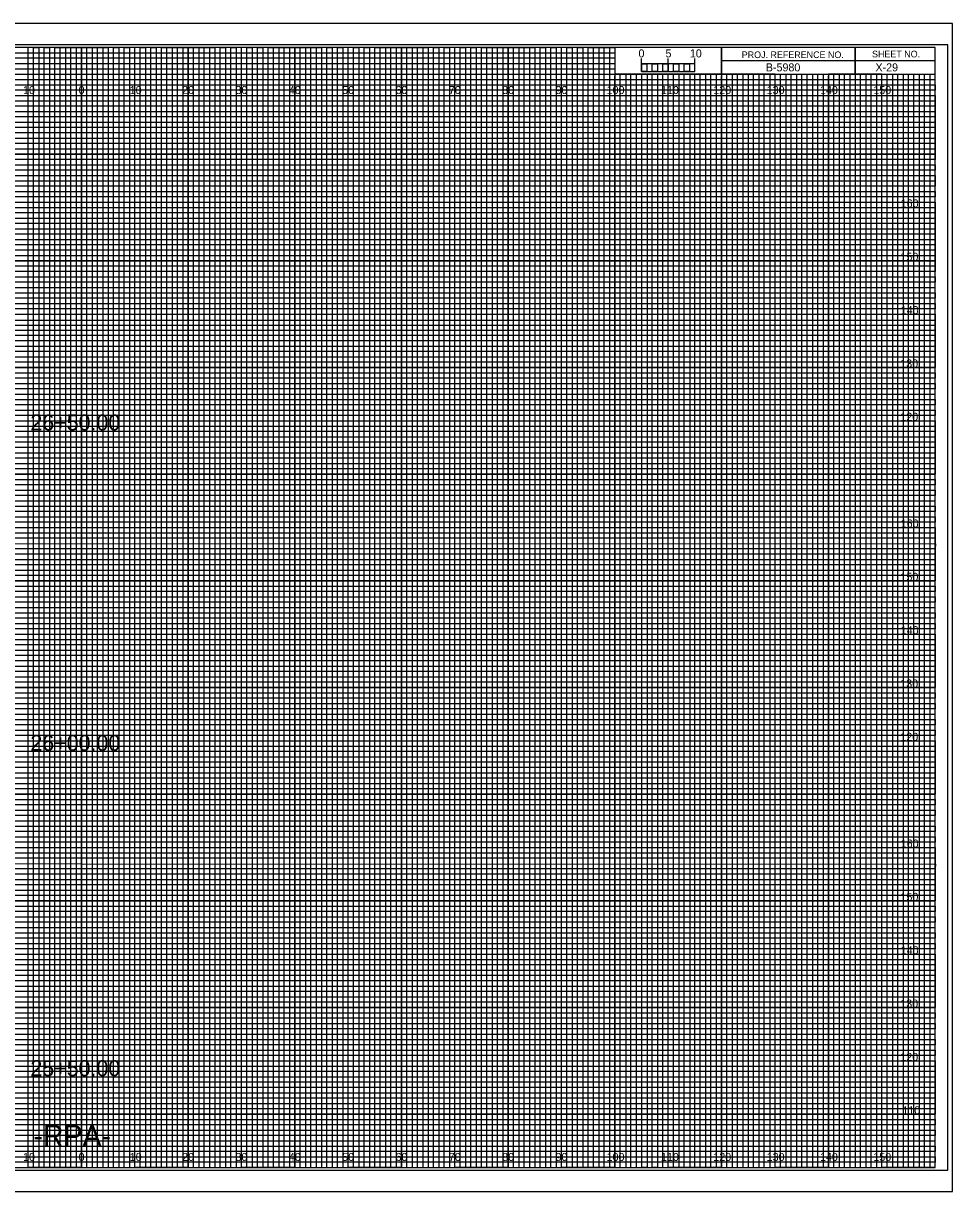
# Model space of a CAD drawing. Extents: x -13 to 323, y -5 to 1974.
# Drawn here: x 149.1 to 323.3, y 1095.5 to 1314.5 of the extents above; entities that cross this region are included whole.
import ezdxf

# ---------------------------------------------------------------- set-up
doc = ezdxf.new("R2010")
doc.units = 0
for name, color, linetype in [('Exist Cross Section Cell', 7, 'Continuous'), ('Exist XS Center Line Elevation Label', 7, 'Continuous'), ('Exist XS Ground Line', 7, 'Continuous'), ('Prop CMT Bridge Girder Bottom Critical Point Inside', 7, 'Continuous'), ('Prop CMT Guardrail Graphics', 7, 'Continuous'), ('Prop CMT Guardrail Widen Shoulder', 7, 'Continuous'), ('Prop CMT Pvmt Course 1', 7, 'Continuous'), ('Prop CMT Pvmt Course 2', 7, 'Continuous'), ('Prop CMT Pvmt Course 3', 7, 'Continuous'), ('Prop CMT Pvmt Surface', 7, 'Continuous'), ('Prop CMT Pvmt Surface Shoulder', 7, 'Continuous'), ('Prop CMT Shld Paved Course 1', 7, 'Continuous'), ('Prop CMT Shld Paved Course 2', 7, 'Continuous'), ('Prop CMT Shld Paved Course 3', 7, 'Continuous'), ('Prop CMT Slope Grass', 7, 'Continuous'), ('Prop CMT Subgrade Earthwork', 7, 'Continuous'), ('Scratch_Level_1', 7, 'Continuous')]:
    doc.layers.add(name, color=color, linetype=linetype)

msp = doc.modelspace()

# ---------------------------------------------------------------- linework, layer by layer
at = {"layer": 'Exist XS Center Line Elevation Label'}
for points in [[(145, 1100), (155, 1100), (155, 1310), (165, 1310), (165, 1100), (175, 1100), (175, 1310), (185, 1310), (185, 1100), (195, 1100), (195, 1310), (205, 1310), (205, 1100), (215, 1100), (215, 1310), (225, 1310), (225, 1100), (235, 1100), (235, 1310), (245, 1310), (245, 1100), (255, 1100), (255, 1310), (259.93, 1310), (260, 1310), (260, 1305), (264.99, 1305), (264.99, 1100), (275, 1100), (275, 1305), (285, 1305), (285, 1100), (295, 1100), (295, 1305), (305, 1305), (305, 1100), (315, 1100), (315, 1305)], [(0, 1305), (275, 1305)], [(0, 1285), (320, 1285), (320, 1295), (0, 1295)], [(0, 1265), (320, 1265), (320, 1275), (0, 1275)], [(0, 1245), (320, 1245), (320, 1255), (0, 1255)], [(0, 1225), (320, 1225), (320, 1235), (0, 1235)], [(0, 1205), (320, 1205), (320, 1215), (0, 1215)], [(0, 1185), (320, 1185), (320, 1195), (0, 1195)], [(0, 1165), (320, 1165), (320, 1175), (0, 1175)], [(0, 1145), (320, 1145), (320, 1155), (0, 1155)], [(0, 1125), (320, 1125), (320, 1135), (0, 1135)], [(0, 1105), (320, 1105), (320, 1115), (0, 1115)]]:
    msp.add_lwpolyline(points, dxfattribs=at)
at = {"layer": 'Exist XS Ground Line'}
for p, q in [((150, 1310), (140, 1310)), ((150, 1100), (150, 1310)), ((170, 1310), (160, 1310)), ((160, 1310), (160, 1100)), ((170, 1100), (170, 1310)), ((190, 1310), (180, 1310)), ((180, 1310), (180, 1100)), ((190, 1100), (190, 1310)), ((210, 1310), (200, 1310)), ((200, 1310), (200, 1100)), ((210, 1100), (210, 1310)), ((230, 1310), (220, 1310)), ((220, 1310), (220, 1100)), ((230, 1100), (230, 1310)), ((250, 1310), (240, 1310)), ((240, 1310), (240, 1100)), ((250, 1100), (250, 1310)), ((260, 1310), (260, 1100)), ((270, 1100), (270, 1305)), ((290, 1305), (280, 1305)), ((280, 1305), (280, 1100)), ((290, 1100), (290, 1305)), ((310, 1305), (300, 1305)), ((300, 1305), (300, 1100)), ((310, 1100), (310, 1305)), ((160, 1100), (150, 1100)), ((180, 1100), (170, 1100)), ((200, 1100), (190, 1100)), ((220, 1100), (210, 1100)), ((240, 1100), (230, 1100)), ((260, 1100), (250, 1100)), ((280, 1100), (270, 1100)), ((300, 1100), (290, 1100)), ((320, 1100), (310, 1100)), ((320, 1100), (320, 1100))]:
    msp.add_line(p, q, dxfattribs=at)
for points in [[(0, 1300), (320, 1300), (320, 1290), (0, 1290)], [(0, 1280), (320, 1280), (320, 1270), (0, 1270)], [(0, 1260), (320, 1260), (320, 1250), (0, 1250)], [(0, 1240), (320, 1240), (320, 1230), (0, 1230)], [(0, 1220), (320, 1220), (320, 1210), (0, 1210)], [(0, 1200), (320, 1200), (320, 1190), (0, 1190)], [(0, 1180), (320, 1180), (320, 1170), (0, 1170)], [(0, 1160), (320, 1160), (320, 1150), (0, 1150)], [(0, 1140), (320, 1140), (320, 1130), (0, 1130)], [(0, 1120), (320, 1120), (320, 1110), (0, 1110)]]:
    msp.add_lwpolyline(points, dxfattribs=at)
at = {"layer": 'Prop CMT Pvmt Course 2'}
for p, q in [((265, 1305.49), (265, 1307.9)), ((265, 1306.9), (265, 1307.9)), ((270, 1305.49), (270, 1307.9)), ((275, 1305.49), (275, 1307.9)), ((275, 1306.9), (275, 1307.9))]:
    msp.add_line(p, q, dxfattribs=at)
for points in [[(275, 1306.9), (265, 1306.9), (265, 1305.49), (275, 1305.49)], [(265, 1306.9), (266, 1306.9), (266, 1305.49), (265, 1305.49)], [(267, 1306.9), (268, 1306.9), (268, 1305.49), (267, 1305.49)], [(269, 1306.9), (270, 1306.9), (270, 1305.49), (269, 1305.49)], [(271, 1306.9), (272, 1306.9), (272, 1305.49), (271, 1305.49)], [(273, 1306.9), (274, 1306.9), (274, 1305.49), (273, 1305.49)]]:
    msp.add_lwpolyline(points, close=True, dxfattribs=at)
at = {"layer": 'Prop CMT Pvmt Course 3'}
msp.add_lwpolyline([(-13.4, 1095.5), (323.3, 1095.5), (323.3, 1314.5), (-13.4, 1314.5)], close=True, dxfattribs=at)
at = {"layer": 'Prop CMT Pvmt Surface'}
for p, q in [((150, 1100), (150, 1310)), ((160, 1100), (160, 1310)), ((170, 1100), (170, 1310)), ((180, 1100), (180, 1310)), ((190, 1100), (190, 1310)), ((200, 1100), (200, 1310)), ((210, 1100), (210, 1310)), ((220, 1100), (220, 1310)), ((230, 1100), (230, 1310)), ((240, 1100), (240, 1310)), ((250, 1100), (250, 1310)), ((260, 1100), (260, 1304.69)), ((270, 1100), (270, 1304.69)), ((280, 1100), (280, 1304.69)), ((290, 1100), (290, 1304.69)), ((300, 1100), (300, 1304.69)), ((310, 1100), (310, 1304.69)), ((0, 1300), (320, 1300)), ((0, 1290), (320, 1290)), ((0, 1280), (320, 1280)), ((0, 1270), (320, 1270)), ((0, 1260), (320, 1260)), ((0, 1250), (320, 1250)), ((0, 1240), (320, 1240)), ((0, 1230), (320, 1230)), ((0, 1220), (320, 1220)), ((0, 1210), (320, 1210)), ((0, 1200), (320, 1200)), ((0, 1190), (320, 1190)), ((0, 1180), (320, 1180)), ((0, 1170), (320, 1170)), ((0, 1160), (320, 1160)), ((0, 1150), (320, 1150)), ((0, 1140), (320, 1140)), ((0, 1130), (320, 1130)), ((0, 1120), (320, 1120)), ((0, 1110), (320, 1110))]:
    msp.add_line(p, q, dxfattribs=at)
at = {"layer": 'Prop CMT Pvmt Surface Shoulder'}
for p, q in [((323.3, 1314.5), (-13.4, 1314.5)), ((-13.4, 1095.5), (323.3, 1095.5))]:
    msp.add_line(p, q, dxfattribs=at)
at = {"layer": 'Prop CMT Shld Paved Course 1'}
for p, q in [((0, 1309), (260, 1309)), ((260, 1307.98), (0, 1307.98)), ((260, 1309), (260, 1307.98)), ((0, 1307), (260, 1307)), ((260, 1305.89), (0, 1305.89)), ((260, 1307), (260, 1305.89)), ((0, 1304), (320, 1304))]:
    msp.add_line(p, q, dxfattribs=at)
for points in [[(0, 1303), (270, 1303), (320, 1303), (320, 1302), (0, 1302)], [(0, 1301), (320, 1301), (320, 1299), (0, 1299)], [(0, 1298), (320, 1298), (320, 1297), (0, 1296.98)], [(0, 1296), (320, 1296), (320, 1294), (0, 1294)], [(0, 1293), (320, 1293), (320, 1292), (0, 1292)], [(0, 1291), (320, 1291), (320, 1289), (0, 1289)], [(0, 1288), (320, 1288), (320, 1287), (0, 1287)], [(0, 1286), (320, 1286), (320, 1284), (0, 1284)], [(0, 1283), (320, 1283), (320, 1282), (0, 1282)], [(0, 1281), (320, 1281), (320, 1279), (0, 1279)], [(0, 1278), (320, 1278), (320, 1277), (0, 1277)], [(0, 1276), (320, 1276), (320, 1273.95), (320, 1273), (320, 1272), (0, 1272)], [(0, 1274), (320, 1274), (320, 1273), (0, 1273)], [(0, 1271), (320, 1271), (320, 1269), (0, 1269.03)], [(0, 1269.03), (320, 1269), (320, 1268), (0, 1268)], [(0, 1267), (320, 1267), (320, 1266), (0, 1266)], [(0, 1264), (320, 1264), (320, 1263), (0, 1263)], [(0, 1262), (320, 1262), (320, 1261), (0, 1261)], [(-0.07, 1258.89), (320, 1258.89), (320, 1257.88), (-0.07, 1257.88)], [(0, 1257), (320, 1257), (320, 1256), (0, 1256)], [(0, 1254), (320, 1254), (320, 1253), (0, 1253)], [(0, 1252), (320, 1252), (320, 1251), (0, 1251)], [(0, 1249), (320, 1249), (320, 1248), (0, 1248)], [(0, 1247), (320, 1247), (320, 1246), (0, 1246)], [(0, 1244), (320, 1244), (320, 1243), (0, 1243)], [(0, 1242), (320, 1242), (320, 1241), (0, 1241)], [(0, 1239), (320, 1239), (319.99, 1237.98), (0, 1238)], [(0, 1237), (320, 1237), (320, 1236), (0, 1236)], [(0, 1234), (320, 1234), (320, 1233), (0, 1233)], [(0, 1232), (320, 1232), (320, 1231), (0, 1231)], [(0, 1229), (320, 1229), (320, 1228), (0, 1228)], [(0, 1227), (320, 1227), (320, 1226), (0, 1226)], [(0, 1224), (320, 1224), (320, 1223), (0, 1223)], [(0, 1222), (320, 1222), (320, 1221), (0, 1221)], [(0, 1219), (320, 1219), (320, 1218), (0, 1218)], [(0, 1216.99), (320.07, 1216.91), (320, 1216), (0, 1216)], [(0, 1214), (320, 1214), (320, 1213), (0, 1213)], [(0, 1212), (320, 1212), (320, 1211), (0, 1211)], [(0, 1209), (320, 1209), (320, 1208), (0, 1208)], [(0, 1207), (320, 1207), (320, 1206), (0, 1206)], [(0, 1204), (320, 1204), (320, 1203), (0, 1203)], [(0, 1202), (320, 1202), (320, 1201), (0, 1201)], [(0, 1199), (320, 1199), (320, 1198), (0, 1198)], [(0, 1197), (320, 1197), (320, 1196), (0, 1196)], [(0, 1194), (320, 1194), (320, 1193), (0, 1193)], [(0, 1192), (320, 1192), (320, 1191), (0, 1191)], [(0, 1189), (320, 1189), (320, 1188), (0, 1188)], [(0, 1187), (320, 1187), (320, 1186), (0, 1186)], [(0, 1184), (320, 1184), (320, 1183), (0, 1183)], [(0, 1182), (320, 1182), (320, 1181), (0, 1181)], [(0, 1179), (320, 1179), (319.99, 1177.98), (0, 1178)], [(0, 1177), (320, 1177), (320, 1176), (0, 1176)], [(0, 1174), (320, 1174), (320, 1173), (0, 1173)], [(0, 1172), (320, 1172), (320, 1171), (0, 1171)], [(0, 1169), (320, 1169), (320, 1168), (0, 1168)], [(0, 1167), (320, 1167), (320, 1166), (0, 1166)], [(0, 1164), (320, 1164), (320, 1163), (0, 1163)], [(0, 1162), (320, 1162), (320, 1161), (0, 1161)], [(0, 1159), (320, 1159), (320, 1158), (0, 1158)], [(0, 1156.99), (320.07, 1156.91), (320, 1156), (0, 1156)], [(0, 1154), (320, 1154), (320, 1153), (0, 1153)], [(0, 1152), (320, 1152), (320, 1151), (0, 1151)], [(0, 1149), (320, 1149), (320, 1148), (0, 1148)], [(0, 1147), (320, 1147), (320, 1146), (0, 1146)], [(0, 1144), (320, 1144), (320, 1143), (0, 1143)], [(0, 1142), (320, 1142), (320, 1141), (0, 1141)], [(0, 1139), (320, 1139), (320, 1138), (0, 1138)], [(0, 1137), (320, 1137), (320, 1136), (0, 1136)], [(0, 1134), (320, 1134), (320, 1133), (0, 1133)], [(0, 1132), (320, 1132), (320, 1131), (0, 1131)], [(0, 1129), (320, 1129), (320, 1128), (0, 1128)], [(0, 1127), (320, 1127), (320, 1126), (0, 1126)], [(0, 1124), (320, 1124), (320, 1123), (0, 1123)], [(0, 1122), (320, 1122), (320, 1121), (0, 1121)], [(0, 1119), (320, 1119), (320, 1118), (0, 1118)], [(0, 1117), (320, 1117), (320, 1116), (0, 1116)], [(0, 1114), (320, 1114), (320, 1113), (0, 1113)], [(0, 1112), (320, 1112), (320, 1111), (0, 1111)], [(0, 1109), (320, 1109), (320, 1108), (0, 1108)], [(0, 1107), (320, 1107), (320, 1106), (0, 1106)], [(0, 1104), (320, 1104), (320, 1103), (0, 1103)], [(0, 1102), (320, 1102), (320, 1101), (0, 1101)]]:
    msp.add_lwpolyline(points, dxfattribs=at)
at = {"layer": 'Prop CMT Shld Paved Course 2'}
for p, q in [((305, 1310), (305, 1305)), ((305, 1305), (305, 1310)), ((280, 1307.5), (280, 1305)), ((320, 1307.49), (280, 1307.49)), ((280, 1305), (320, 1305))]:
    msp.add_line(p, q, dxfattribs=at)
for points in [[(320, 1310), (0, 1310), (0, 1100), (320, 1100)], [(280, 1310), (260, 1310), (260, 1305.03), (280, 1305.03)], [(320, 1310), (280, 1310), (280, 1305), (320, 1305)]]:
    msp.add_lwpolyline(points, close=True, dxfattribs=at)
at = {"layer": 'Prop CMT Shld Paved Course 3'}
for p, q in [((267, 1305), (266.01, 1305)), ((266.01, 1305), (266.01, 1100)), ((267, 1100), (267, 1305)), ((269, 1305), (268, 1305)), ((268, 1305), (268, 1100)), ((269, 1100), (269, 1305)), ((266.01, 1100), (265, 1100)), ((268, 1100), (267, 1100))]:
    msp.add_line(p, q, dxfattribs=at)
for points in [[(150, 1100), (151, 1100), (151, 1310), (152, 1310), (152, 1100)], [(152, 1100), (153, 1100), (153, 1310), (154, 1310), (154, 1100)], [(155, 1100), (156, 1100), (156, 1310), (157, 1310), (157, 1100)], [(157, 1100), (158, 1100), (158, 1310), (159, 1310), (159, 1100)], [(160, 1100), (161, 1100), (161, 1310), (162, 1310), (162, 1100)], [(162, 1100), (163, 1100), (163, 1310), (164, 1310), (164, 1100)], [(165, 1100), (166, 1100), (166, 1310), (167, 1310), (167, 1100)], [(167, 1100), (168, 1100), (168, 1310), (169, 1310), (169, 1100)], [(170, 1100), (171, 1100), (171, 1310), (172, 1310), (172, 1100)], [(172, 1100), (173, 1100), (173, 1310), (174, 1310), (174, 1100)], [(175, 1100), (176, 1100), (176, 1310), (177, 1310), (177, 1100)], [(177, 1100), (178, 1100), (178, 1310), (179, 1310), (179, 1100)], [(180, 1100), (181, 1100), (181, 1310), (182, 1310), (182, 1100)], [(182, 1100), (183, 1100), (183, 1310), (184, 1310), (184, 1100)], [(185, 1100), (186, 1100), (186, 1310), (187, 1310), (187, 1100)], [(187, 1100), (188, 1100), (188, 1310), (189, 1310), (189, 1100)], [(190, 1100), (191, 1100), (191, 1310), (192, 1310), (192, 1100)], [(192, 1100), (193, 1100), (193, 1310), (194, 1310), (194, 1100)], [(195, 1100), (196, 1100), (196, 1310), (197, 1310), (197, 1100)], [(197, 1100), (198, 1100), (198, 1310), (199, 1310), (199, 1100)], [(200, 1100), (201, 1100), (201, 1310), (202, 1310), (202, 1100)], [(202, 1100), (203, 1100), (203, 1310), (204, 1310), (204, 1100)], [(205, 1100), (206, 1100), (206, 1310), (207, 1310), (207, 1100)], [(207, 1100), (208, 1100), (208, 1310), (209, 1310), (209, 1100)], [(210, 1100), (211, 1100), (211, 1310), (212, 1310), (212, 1100)], [(212, 1100), (213, 1100), (213, 1310), (214, 1310), (214, 1100)], [(215, 1100), (216, 1100), (216, 1310), (217, 1310), (217, 1100)], [(217, 1100), (218, 1100), (218, 1310), (219, 1310), (219, 1100)], [(220, 1100), (221, 1100), (221, 1310), (222, 1310), (222, 1100)], [(222, 1100), (223, 1100), (223, 1310), (224, 1310), (224, 1100)], [(225, 1100), (226, 1100), (226, 1310), (227, 1310), (227, 1100)], [(227, 1100), (228, 1100), (228, 1310), (229, 1310), (229, 1100)], [(230, 1100), (231, 1100), (231, 1310), (232, 1310), (232, 1100)], [(232, 1100), (233, 1100), (233, 1310), (234, 1310), (234, 1100)], [(235, 1100), (236, 1100), (236, 1310), (237, 1310), (237, 1100)], [(237, 1100), (238, 1100), (238, 1310), (239, 1310), (239, 1100)], [(240, 1100), (241, 1100), (241, 1310), (242, 1310), (242, 1100)], [(242, 1100), (243, 1100), (243, 1310), (244, 1310), (244, 1100)], [(245, 1100), (246, 1100), (246, 1310), (247, 1310), (247, 1100)], [(247, 1100), (248, 1100), (248, 1310), (249, 1310), (249, 1100)], [(250, 1100), (251, 1100), (251, 1310), (252, 1310), (252, 1100)], [(252, 1100), (253, 1100), (253, 1310), (254, 1310), (254, 1100)], [(255, 1100), (256, 1100), (256, 1310), (257, 1310), (257, 1100)], [(257, 1100), (258, 1100), (258, 1310), (259, 1310), (259, 1100)], [(260, 1100), (261, 1100), (261, 1305), (262.02, 1305), (262.02, 1100)], [(262, 1100), (263, 1100), (263, 1305), (263.99, 1305), (263.99, 1100)], [(270, 1100), (270.98, 1100), (270.98, 1305), (272, 1305), (272, 1100)], [(272, 1100), (273, 1100), (273, 1305), (274.05, 1305), (274.05, 1100)], [(275, 1100), (276, 1100), (276, 1305), (277, 1305), (277, 1100)], [(277, 1100), (278, 1100), (278, 1305), (279, 1305), (279, 1100)], [(280, 1100), (281, 1100), (281, 1305), (282, 1305), (282, 1100)], [(282, 1100), (283, 1100), (283, 1305), (284, 1305), (284, 1100)], [(285, 1100), (286, 1100), (286, 1305), (287, 1305), (287, 1100)], [(287, 1100), (288, 1100), (288, 1305), (289, 1305), (289, 1100)], [(290, 1100), (291, 1100), (291, 1305), (292, 1305), (292, 1100)], [(292, 1100), (293, 1100), (293, 1305), (294, 1305), (294, 1100)], [(295, 1100), (296, 1100), (296, 1305), (297, 1305), (297, 1100)], [(297, 1100), (298, 1100), (298, 1305), (299, 1305), (299, 1100)], [(300, 1100), (301, 1100), (301, 1305), (302, 1305), (302, 1100)], [(302, 1100), (303, 1100), (303, 1305), (304, 1305), (304, 1100)], [(305, 1100), (306, 1100), (306, 1305), (307, 1305), (307, 1100)], [(307, 1100), (308, 1100), (308, 1305), (309, 1305), (309, 1100)], [(310, 1100), (311, 1100), (311, 1305), (312, 1305), (312, 1100)], [(312, 1100), (313, 1100), (313, 1305), (314, 1305), (314, 1100)], [(315, 1100), (316, 1100), (316, 1305), (317, 1305), (317, 1100)], [(317, 1100), (318, 1100), (318, 1305), (319, 1305), (319, 1100)]]:
    msp.add_lwpolyline(points, dxfattribs=at)
at = {"layer": 'Prop CMT Subgrade Earthwork'}
msp.add_lwpolyline([(-10.8, 1099.5), (322.4, 1099.5), (322.4, 1310.5), (-10.8, 1310.5)], close=True, dxfattribs=at)

# ---------------------------------------------------------------- texts
at = {"layer": 'Exist Cross Section Cell'}
for s, p in [('10', (149.04, 1301.25)), ('0', (159.45, 1301.25)), ('0', (159.45, 1301.25)), ('10', (169.04, 1301.25)), ('20', (178.86, 1301.25)), ('30', (188.86, 1301.25)), ('40', (198.86, 1301.25)), ('50', (208.86, 1301.25)), ('60', (218.86, 1301.25)), ('70', (228.86, 1301.25)), ('80', (238.86, 1301.25)), ('90', (248.86, 1301.25)), ('100', (258.44, 1301.25)), ('110', (268.62, 1301.25)), ('120', (278.44, 1301.25)), ('130', (288.44, 1301.25)), ('140', (298.44, 1301.25)), ('150', (308.44, 1301.25)), ('10', (149.04, 1101.25)), ('0', (159.45, 1101.25)), ('0', (159.45, 1101.25)), ('10', (169.04, 1101.25)), ('20', (178.86, 1101.25)), ('30', (188.86, 1101.25)), ('40', (198.86, 1101.25)), ('50', (208.86, 1101.25)), ('60', (218.86, 1101.25)), ('70', (228.86, 1101.25)), ('80', (238.86, 1101.25)), ('90', (248.86, 1101.25)), ('100', (258.44, 1101.25)), ('110', (268.62, 1101.25)), ('120', (278.44, 1101.25)), ('130', (288.44, 1101.25)), ('140', (298.44, 1101.25)), ('150', (308.44, 1101.25))]:
    msp.add_text(s, height=1.5, dxfattribs=at).set_placement(p)
at = {"layer": 'Prop CMT Bridge Girder Bottom Critical Point Inside'}
for s, p in [('5', (269.47, 1308.12)), ('10', (274.04, 1308.12))]:
    msp.add_text(s, height=1.5, dxfattribs=at).set_placement(p)
at = {"layer": 'Prop CMT Guardrail Graphics'}
msp.add_text('B-5980', height=1.5, dxfattribs=at).set_placement((288.28, 1305.5))
at = {"layer": 'Prop CMT Guardrail Widen Shoulder'}
msp.add_text('X-29', height=1.5, dxfattribs=at).set_placement((308.83, 1305.5))
at = {"layer": 'Prop CMT Pvmt Course 1'}
for s, p in [('160', (313.57, 1280)), ('150', (313.52, 1270)), ('140', (313.57, 1260)), ('130', (313.49, 1250)), ('120', (313.5, 1240)), ('160', (313.57, 1220)), ('150', (313.52, 1210)), ('140', (313.57, 1200)), ('130', (313.49, 1190)), ('120', (313.5, 1180)), ('160', (313.57, 1160)), ('150', (313.52, 1150)), ('140', (313.57, 1140)), ('130', (313.49, 1130)), ('120', (313.5, 1120)), ('110', (313.88, 1110))]:
    msp.add_text(s, height=1.5, dxfattribs=at).set_placement(p)
at = {"layer": 'Prop CMT Pvmt Course 2'}
msp.add_text('0', height=1.5, dxfattribs=at).set_placement((264.41, 1308.12))
at = {"layer": 'Prop CMT Shld Paved Course 2'}
for s, p in [('PROJ. REFERENCE NO.', (283.77, 1307.99)), ('SHEET NO.', (308.19, 1308.12))]:
    msp.add_text(s, height=1.25, dxfattribs=at).set_placement(p)
at = {"layer": 'Prop CMT Slope Grass'}
for s, p in [('26+50.00', (150.41, 1238.19)), ('26+00.00', (150.41, 1178.12)), ('25+50.00', (150.41, 1117.14))]:
    msp.add_text(s, height=3, dxfattribs=at).set_placement(p)
at = {"layer": 'Scratch_Level_1'}
msp.add_text('-RPA-', height=4, dxfattribs=at).set_placement((150.97, 1104))

doc.saveas('drawing.dxf')
